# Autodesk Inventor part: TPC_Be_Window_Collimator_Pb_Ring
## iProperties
Shininess: 64.0
Length Units: 11269
Angle Units: 11279
Time Units: 11290
Mass Units: 11283
Length Display Precision: 3
Angle Display Precision: 2
Compacted: True
Part Number: TPC_Be_Window_Collimator_Pb_Ring
Document SubType Name: Modeling
Created: 2004-07
Material: Lead
Designer: John Blackburn
Manufacturer: Standard
Standards Organization: Custom
Project: mucap
Description: Be Window Collimator Cap
Density: 0.0
Volumn: 0.0
Area: 0.0
PropertySet Name: Model Information
Control State: 0
Master: False
Checked Out: False
Author: John Blackburn
Title: Be Window Collimator Cap
Subject: mucap
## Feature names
1. Extrusion1
2. Hole1
3. Circular Pattern1
4. Extrusion3
